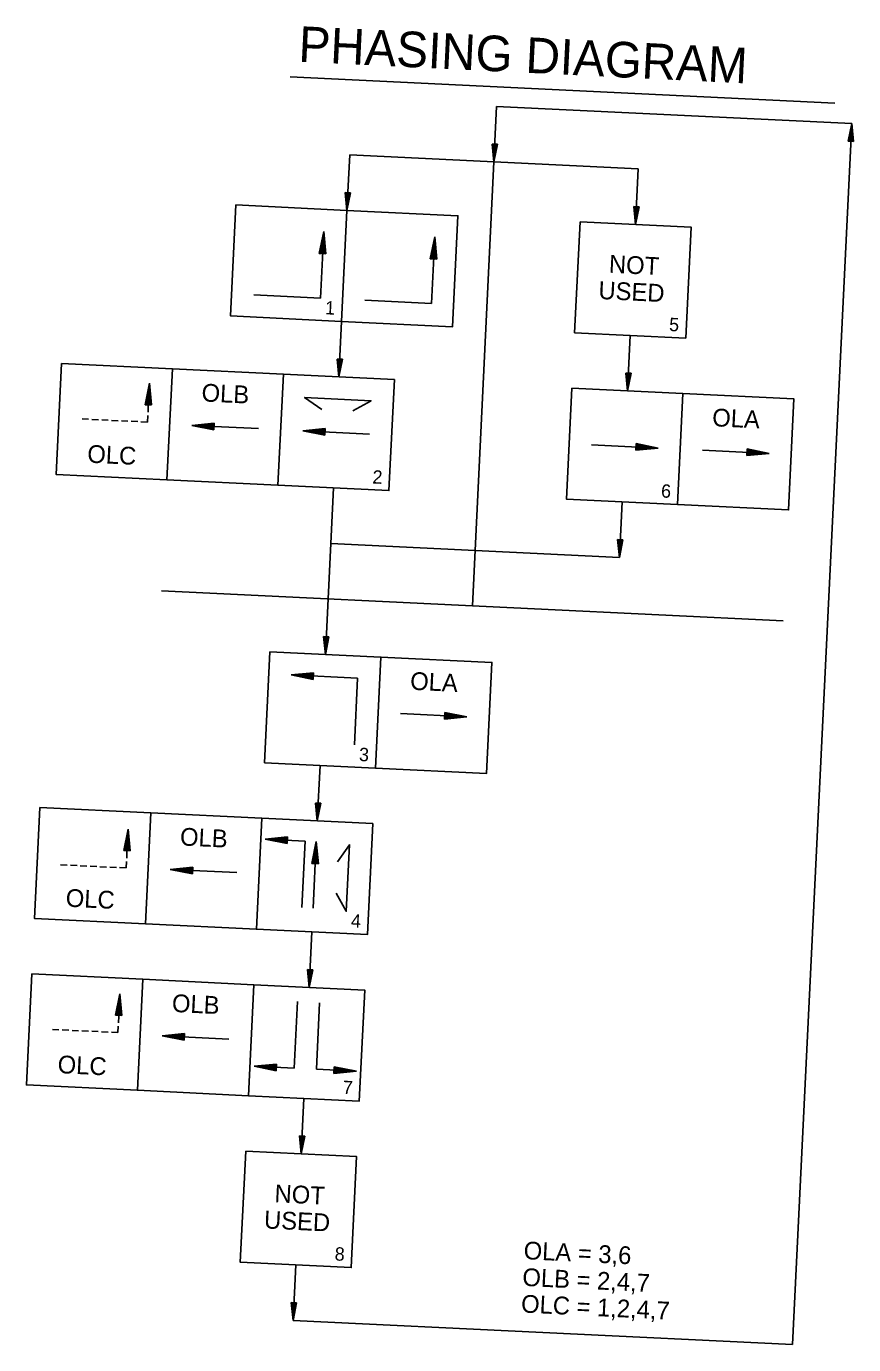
# Model space of a CAD drawing. Extents: x 662220 to 671027, y 641390 to 743815.
# Drawn here: x 662237 to 662423.1, y 642449.9 to 642746.5 of the extents above; entities that cross this region are included whole.
import ezdxf

# ---------------------------------------------------------------- set-up
doc = ezdxf.new("R2010")
doc.units = 0
doc.layers.add('R_Proposed Road Annot', color=7, linetype='Continuous')

msp = doc.modelspace()

# ---------------------------------------------------------------- linework, layer by layer
at = {"layer": 'R_Proposed Road Annot'}
for p, q in [((662296.37, 642735.15), (662418.88, 642729.2)), ((662337.38, 642616.11), (662342.83, 642728.48)), ((662342.83, 642728.48), (662422.74, 642724.6)), ((662422.74, 642724.6), (662409.4, 642449.92)), ((662421.95, 642720.63), (662422.74, 642724.6)), ((662422.05, 642720.63), (662422.71, 642723.93)), ((662422.15, 642720.62), (662422.67, 642723.25)), ((662422.25, 642720.62), (662422.64, 642722.58)), ((662422.84, 642720.59), (662422.64, 642722.58)), ((662422.94, 642720.59), (662422.67, 642723.25)), ((662423.04, 642720.58), (662422.71, 642723.93)), ((662423.14, 642720.58), (662422.74, 642724.6)), ((662341.82, 642720.02), (662342.23, 642716)), ((662343.02, 642719.96), (662341.82, 642720.02)), ((662341.92, 642720.01), (662342.26, 642716.66)), ((662342.02, 642720.01), (662342.29, 642717.35)), ((662342.12, 642720.01), (662342.32, 642718.01)), ((662342.23, 642720), (662342.36, 642718.69)), ((662343.02, 642719.96), (662342.23, 642716)), ((662342.92, 642719.97), (662342.26, 642716.66)), ((662342.82, 642719.97), (662342.29, 642717.35)), ((662342.72, 642719.98), (662342.32, 642718.01)), ((662342.33, 642720), (662342.39, 642719.36)), ((662342.61, 642719.98), (662342.36, 642718.69)), ((662342.51, 642719.99), (662342.39, 642719.36)), ((662421.95, 642720.63), (662423.14, 642720.58)), ((662422.35, 642720.61), (662422.61, 642721.9)), ((662422.45, 642720.61), (662422.58, 642721.24)), ((662422.64, 642720.6), (662422.58, 642721.24)), ((662422.74, 642720.6), (662422.61, 642721.9)), ((662309.16, 642705.09), (662309.77, 642717.57)), ((662309.77, 642717.57), (662374.69, 642714.42)), ((662374.08, 642701.93), (662374.69, 642714.42)), ((662308.75, 642709.11), (662309.16, 642705.09)), ((662309.95, 642709.05), (662308.75, 642709.11)), ((662308.85, 642709.11), (662309.19, 642705.75)), ((662308.96, 642709.1), (662309.22, 642706.44)), ((662309.06, 642709.1), (662309.26, 642707.11)), ((662309.16, 642709.09), (662309.29, 642707.78)), ((662309.95, 642709.05), (662309.16, 642705.09)), ((662309.85, 642709.06), (662309.19, 642705.75)), ((662309.75, 642709.06), (662309.22, 642706.44)), ((662309.26, 642709.09), (662309.32, 642708.45)), ((662309.65, 642709.07), (662309.26, 642707.11)), ((662309.55, 642709.07), (662309.29, 642707.78)), ((662309.45, 642709.08), (662309.32, 642708.45)), ((662373.68, 642705.96), (662374.08, 642701.93)), ((662374.88, 642705.9), (662373.68, 642705.96)), ((662373.78, 642705.95), (662374.11, 642702.6)), ((662373.88, 642705.95), (662374.15, 642703.29)), ((662373.98, 642705.94), (662374.18, 642703.95)), ((662374.08, 642705.94), (662374.21, 642704.63)), ((662374.88, 642705.9), (662374.08, 642701.93)), ((662374.78, 642705.9), (662374.11, 642702.6)), ((662374.67, 642705.91), (662374.15, 642703.29)), ((662374.18, 642705.93), (662374.25, 642705.3)), ((662374.57, 642705.91), (662374.18, 642703.95)), ((662374.47, 642705.92), (662374.21, 642704.63)), ((662374.37, 642705.92), (662374.25, 642705.3)), ((662302.93, 642695.38), (662303.92, 642700.33)), ((662303.88, 642699.5), (662303.06, 642695.37)), ((662303.18, 642695.36), (662303.84, 642698.64)), ((662303.19, 642685.35), (662303.92, 642700.33)), ((662303.84, 642698.64), (662304.18, 642695.32)), ((662304.3, 642695.31), (662303.88, 642699.5)), ((662303.92, 642700.33), (662304.43, 642695.3)), ((662327.9, 642694.16), (662328.89, 642699.12)), ((662328.17, 642684.14), (662328.89, 642699.12)), ((662328.89, 642699.12), (662329.4, 642694.09)), ((662303.8, 642697.81), (662303.31, 642695.36)), ((662303.44, 642695.35), (662303.76, 642696.96)), ((662303.72, 642696.13), (662303.56, 642695.35)), ((662303.8, 642695.33), (662303.72, 642696.13)), ((662303.76, 642696.96), (662303.92, 642695.33)), ((662304.05, 642695.32), (662303.8, 642697.81)), ((662328.85, 642698.29), (662328.03, 642694.16)), ((662328.15, 642694.15), (662328.81, 642697.43)), ((662328.77, 642696.6), (662328.28, 642694.15)), ((662328.41, 642694.14), (662328.73, 642695.75)), ((662328.73, 642695.75), (662328.89, 642694.12)), ((662329.02, 642694.11), (662328.77, 642696.6)), ((662328.81, 642697.43), (662329.15, 642694.1)), ((662329.27, 642694.1), (662328.85, 642698.29)), ((662302.93, 642695.38), (662304.43, 642695.3)), ((662327.9, 642694.16), (662329.4, 642694.09)), ((662328.69, 642694.92), (662328.53, 642694.13)), ((662328.77, 642694.12), (662328.69, 642694.92)), ((662288.21, 642686.08), (662303.19, 642685.35)), ((662313.18, 642684.87), (662328.17, 642684.14)), ((662307.34, 642667.63), (662307.95, 642680.12)), ((662372.26, 642664.48), (662372.87, 642676.96)), ((662306.93, 642671.65), (662307.34, 642667.63)), ((662308.13, 642671.6), (662306.93, 642671.65)), ((662307.03, 642671.65), (662307.37, 642668.3)), ((662307.14, 642671.65), (662307.41, 642668.98)), ((662307.24, 642671.64), (662307.44, 642669.65)), ((662307.34, 642671.64), (662307.47, 642670.33)), ((662308.13, 642671.6), (662307.34, 642667.63)), ((662308.03, 642671.6), (662307.37, 642668.3)), ((662307.93, 642671.61), (662307.41, 642668.98)), ((662307.44, 642671.63), (662307.5, 642670.99)), ((662307.83, 642671.61), (662307.44, 642669.65)), ((662307.73, 642671.62), (662307.47, 642670.33)), ((662307.63, 642671.62), (662307.5, 642670.99)), ((662263.76, 642661.38), (662264.72, 642666.2)), ((662264.72, 642666.2), (662265.21, 642661.31)), ((662371.86, 642668.5), (662372.26, 642664.48)), ((662373.06, 642668.44), (662371.86, 642668.5)), ((662371.96, 642668.5), (662372.3, 642665.15)), ((662372.06, 642668.49), (662372.33, 642665.83)), ((662372.16, 642668.49), (662372.36, 642666.5)), ((662372.26, 642668.48), (662372.39, 642667.17)), ((662373.06, 642668.44), (662372.26, 642664.48)), ((662372.96, 642668.45), (662372.3, 642665.15)), ((662372.85, 642668.45), (662372.33, 642665.83)), ((662372.36, 642668.48), (662372.43, 642667.84)), ((662372.76, 642668.46), (662372.36, 642666.5)), ((662372.65, 642668.46), (662372.39, 642667.17)), ((662372.55, 642668.47), (662372.43, 642667.84)), ((662264.68, 642665.39), (662263.88, 642661.37)), ((662264, 642661.37), (662264.64, 642664.55)), ((662264.6, 642663.74), (662264.12, 642661.36)), ((662264.85, 642661.32), (662264.6, 642663.74)), ((662264.64, 642664.55), (662264.97, 642661.32)), ((662265.09, 642661.31), (662264.68, 642665.39)), ((662263.76, 642661.38), (662265.21, 642661.31)), ((662264.25, 642661.35), (662264.56, 642662.92)), ((662264.52, 642662.11), (662264.37, 642661.35)), ((662264.47, 642661.14), (662264.4, 642659.67)), ((662264.6, 642661.34), (662264.52, 642662.11)), ((662264.56, 642662.92), (662264.72, 642661.33)), ((662249.55, 642658.17), (662251.03, 642658.1)), ((662251.76, 642658.07), (662253.24, 642658)), ((662253.98, 642657.96), (662255.45, 642657.89)), ((662256.19, 642657.85), (662257.66, 642657.78)), ((662258.4, 642657.74), (662259.87, 642657.67)), ((662260.61, 642657.64), (662262.08, 642657.57)), ((662262.82, 642657.53), (662264.3, 642657.46)), ((662264.37, 642658.93), (662264.3, 642657.46)), ((662274.27, 642656.72), (662279.3, 642657.23)), ((662279.3, 642657.1), (662275.11, 642656.68)), ((662279.23, 642655.73), (662279.3, 642657.23)), ((662289.25, 642655.99), (662274.27, 642656.72)), ((662279.23, 642655.73), (662274.27, 642656.72)), ((662275.11, 642656.68), (662279.24, 642655.85)), ((662275.96, 642656.64), (662279.29, 642656.98)), ((662279.24, 642655.98), (662275.96, 642656.64)), ((662279.28, 642656.85), (662276.8, 642656.6)), ((662276.8, 642656.6), (662279.25, 642656.11)), ((662277.64, 642656.56), (662279.28, 642656.72)), ((662279.25, 642656.24), (662277.64, 642656.56)), ((662279.27, 642656.6), (662278.48, 642656.52)), ((662278.48, 642656.52), (662279.26, 642656.36)), ((662299.24, 642655.51), (662304.27, 642656.02)), ((662314.22, 642654.78), (662299.24, 642655.51)), ((662304.2, 642654.52), (662299.24, 642655.51)), ((662304.27, 642655.89), (662300.08, 642655.47)), ((662300.08, 642655.47), (662304.21, 642654.64)), ((662300.94, 642655.43), (662304.26, 642655.76)), ((662304.21, 642654.77), (662300.94, 642655.43)), ((662304.25, 642655.64), (662301.77, 642655.39)), ((662301.77, 642655.39), (662304.22, 642654.89)), ((662302.61, 642655.35), (662304.25, 642655.51)), ((662304.22, 642655.02), (662302.61, 642655.35)), ((662304.24, 642655.38), (662303.45, 642655.3)), ((662303.45, 642655.3), (662304.23, 642655.15)), ((662304.2, 642654.52), (662304.27, 642656.02)), ((662364.17, 642652.36), (662379.15, 642651.63)), ((662374.19, 642652.62), (662374.12, 642651.12)), ((662374.12, 642651.25), (662378.31, 642651.67)), ((662379.15, 642651.63), (662374.12, 642651.12)), ((662377.46, 642651.71), (662374.13, 642651.37)), ((662375.78, 642651.79), (662374.14, 642651.63)), ((662374.14, 642651.5), (662376.62, 642651.75)), ((662374.15, 642651.75), (662374.94, 642651.83)), ((662374.94, 642651.83), (662374.16, 642651.99)), ((662376.62, 642651.75), (662374.17, 642652.24)), ((662374.17, 642652.11), (662375.78, 642651.79)), ((662378.31, 642651.67), (662374.18, 642652.5)), ((662374.18, 642652.37), (662377.46, 642651.71)), ((662374.19, 642652.62), (662379.15, 642651.63)), ((662389.14, 642651.14), (662404.12, 642650.42)), ((662399.16, 642651.41), (662399.09, 642649.91)), ((662399.15, 642651.16), (662402.43, 642650.5)), ((662399.16, 642651.41), (662404.12, 642650.42)), ((662403.28, 642650.46), (662399.16, 642651.28)), ((662399.09, 642650.03), (662403.28, 642650.46)), ((662404.12, 642650.42), (662399.09, 642649.91)), ((662402.43, 642650.5), (662399.1, 642650.16)), ((662400.75, 642650.58), (662399.11, 642650.41)), ((662399.11, 642650.29), (662401.59, 642650.54)), ((662399.12, 642650.54), (662399.91, 642650.62)), ((662399.91, 642650.62), (662399.13, 642650.78)), ((662401.59, 642650.54), (662399.14, 642651.03)), ((662399.14, 642650.9), (662400.75, 642650.58)), ((662304.31, 642605.2), (662306.13, 642642.66)), ((662370.44, 642627.02), (662371.05, 642639.51)), ((662370.04, 642631.05), (662370.44, 642627.02)), ((662371.24, 642630.99), (662370.04, 642631.05)), ((662370.14, 642631.04), (662370.48, 642627.69)), ((662370.24, 642631.04), (662370.51, 642628.38)), ((662370.34, 642631.03), (662370.54, 642629.04)), ((662370.44, 642631.03), (662370.58, 642629.72)), ((662371.24, 642630.99), (662370.44, 642627.02)), ((662371.14, 642630.99), (662370.48, 642627.69)), ((662371.04, 642631), (662370.51, 642628.38)), ((662370.54, 642631.02), (662370.61, 642630.39)), ((662370.94, 642631), (662370.54, 642629.04)), ((662370.83, 642631.01), (662370.58, 642629.72)), ((662370.73, 642631.01), (662370.61, 642630.39)), ((662305.52, 642630.17), (662370.44, 642627.02)), ((662267.46, 642619.51), (662407.29, 642612.72)), ((662303.9, 642609.23), (662304.31, 642605.2)), ((662305.1, 642609.17), (662303.9, 642609.23)), ((662304, 642609.22), (662304.34, 642605.87)), ((662304.11, 642609.22), (662304.37, 642606.56)), ((662304.2, 642609.21), (662304.41, 642607.22)), ((662304.31, 642609.21), (662304.44, 642607.9)), ((662305.1, 642609.17), (662304.31, 642605.2)), ((662305, 642609.18), (662304.34, 642605.87)), ((662304.9, 642609.18), (662304.37, 642606.56)), ((662304.41, 642609.2), (662304.47, 642608.57)), ((662304.8, 642609.18), (662304.41, 642607.22)), ((662304.7, 642609.19), (662304.44, 642607.9)), ((662304.6, 642609.19), (662304.47, 642608.57)), ((662296.57, 642600.57), (662301.61, 642601.08)), ((662301.6, 642600.96), (662297.41, 642600.53)), ((662298.27, 642600.49), (662301.59, 642600.83)), ((662301.53, 642599.58), (662301.61, 642601.08)), ((662311.56, 642599.85), (662296.57, 642600.57)), ((662301.53, 642599.58), (662296.57, 642600.57)), ((662297.41, 642600.53), (662301.54, 642599.71)), ((662301.54, 642599.83), (662298.27, 642600.49)), ((662301.59, 642600.7), (662299.1, 642600.45)), ((662299.1, 642600.45), (662301.55, 642599.96)), ((662299.95, 642600.41), (662301.58, 642600.58)), ((662301.56, 642600.09), (662299.95, 642600.41)), ((662301.57, 642600.45), (662300.78, 642600.37)), ((662300.78, 642600.37), (662301.56, 642600.21)), ((662310.83, 642584.86), (662311.56, 642599.85)), ((662321.18, 642591.87), (662336.16, 642591.14)), ((662331.21, 642592.13), (662331.13, 642590.64)), ((662331.19, 642591.88), (662334.47, 642591.22)), ((662335.33, 642591.18), (662331.2, 642592.01)), ((662331.21, 642592.13), (662336.16, 642591.14)), ((662336.16, 642591.14), (662331.13, 642590.64)), ((662331.14, 642590.76), (662335.33, 642591.18)), ((662331.15, 642591.01), (662333.64, 642591.27)), ((662334.47, 642591.22), (662331.15, 642590.89)), ((662331.16, 642591.27), (662331.96, 642591.35)), ((662332.79, 642591.31), (662331.16, 642591.14)), ((662331.18, 642591.63), (662332.79, 642591.31)), ((662331.96, 642591.35), (662331.18, 642591.5)), ((662333.64, 642591.27), (662331.19, 642591.76)), ((662302.49, 642567.75), (662303.1, 642580.23)), ((662302.08, 642571.77), (662302.49, 642567.75)), ((662303.28, 642571.71), (662302.08, 642571.77)), ((662302.18, 642571.77), (662302.52, 642568.42)), ((662302.29, 642571.76), (662302.56, 642569.1)), ((662302.39, 642571.76), (662302.59, 642569.77)), ((662302.49, 642571.75), (662302.62, 642570.45)), ((662303.28, 642571.71), (662302.49, 642567.75)), ((662303.18, 642571.72), (662302.52, 642568.42)), ((662303.08, 642571.72), (662302.56, 642569.1)), ((662302.59, 642571.75), (662302.65, 642571.11)), ((662302.98, 642571.73), (662302.59, 642569.77)), ((662302.88, 642571.73), (662302.62, 642570.45)), ((662302.78, 642571.74), (662302.65, 642571.11)), ((662258.95, 642561.07), (662259.91, 642565.89)), ((662259.91, 642565.89), (662260.4, 642561)), ((662259.87, 642565.08), (662259.07, 642561.07)), ((662259.19, 642561.06), (662259.83, 642564.25)), ((662259.79, 642563.44), (662259.31, 642561.06)), ((662259.44, 642561.05), (662259.75, 642562.62)), ((662259.75, 642562.62), (662259.91, 642561.03)), ((662260.04, 642561.02), (662259.79, 642563.44)), ((662259.83, 642564.25), (662260.16, 642561.02)), ((662260.28, 642561.01), (662259.87, 642565.08)), ((662290.78, 642563.65), (662295.81, 642564.15)), ((662299.77, 642563.21), (662290.78, 642563.65)), ((662295.73, 642562.65), (662290.78, 642563.65)), ((662295.8, 642564.03), (662291.61, 642563.6)), ((662291.61, 642563.6), (662295.74, 642562.78)), ((662292.47, 642563.56), (662295.8, 642563.9)), ((662295.75, 642562.91), (662292.47, 642563.56)), ((662295.79, 642563.78), (662293.3, 642563.52)), ((662293.3, 642563.52), (662295.75, 642563.03)), ((662294.15, 642563.48), (662295.78, 642563.65)), ((662295.76, 642563.16), (662294.15, 642563.48)), ((662295.78, 642563.52), (662294.98, 642563.44)), ((662294.98, 642563.44), (662295.77, 642563.29)), ((662295.73, 642562.65), (662295.81, 642564.15)), ((662299.04, 642548.23), (662299.77, 642563.21)), ((662301.27, 642558.13), (662302.26, 642563.09)), ((662302.22, 642562.25), (662301.4, 642558.12)), ((662301.54, 642548.11), (662302.26, 642563.09)), ((662302.65, 642558.06), (662302.22, 642562.25)), ((662302.26, 642563.09), (662302.77, 642558.06)), ((662258.95, 642561.07), (662260.4, 642561)), ((662259.71, 642561.81), (662259.56, 642561.04)), ((662259.67, 642560.84), (662259.6, 642559.37)), ((662259.79, 642561.03), (662259.71, 642561.81)), ((662301.52, 642558.12), (662302.18, 642561.39)), ((662302.14, 642560.56), (662301.65, 642558.11)), ((662301.78, 642558.11), (662302.1, 642559.72)), ((662302.1, 642559.72), (662302.27, 642558.08)), ((662302.39, 642558.08), (662302.14, 642560.56)), ((662302.18, 642561.39), (662302.52, 642558.07)), ((662244.74, 642557.87), (662246.22, 642557.8)), ((662246.96, 642557.76), (662248.43, 642557.69)), ((662249.17, 642557.66), (662250.64, 642557.59)), ((662251.38, 642557.55), (662252.85, 642557.48)), ((662253.59, 642557.44), (662255.06, 642557.37)), ((662255.8, 642557.33), (662257.28, 642557.26)), ((662258.01, 642557.23), (662259.49, 642557.16)), ((662259.56, 642558.63), (662259.49, 642557.16)), ((662269.42, 642556.84), (662274.45, 642557.35)), ((662284.4, 642556.11), (662269.42, 642556.84)), ((662274.38, 642555.85), (662269.42, 642556.84)), ((662274.45, 642557.22), (662270.26, 642556.8)), ((662270.26, 642556.8), (662274.39, 642555.97)), ((662271.11, 642556.76), (662274.44, 642557.09)), ((662274.39, 642556.1), (662271.11, 642556.76)), ((662274.43, 642556.97), (662271.95, 642556.72)), ((662271.95, 642556.72), (662274.4, 642556.22)), ((662272.79, 642556.68), (662274.43, 642556.84)), ((662274.4, 642556.35), (662272.79, 642556.68)), ((662274.42, 642556.71), (662273.63, 642556.64)), ((662273.63, 642556.64), (662274.41, 642556.48)), ((662274.38, 642555.85), (662274.45, 642557.35)), ((662301.27, 642558.13), (662302.77, 642558.06)), ((662302.06, 642558.88), (662301.9, 642558.1)), ((662302.14, 642558.09), (662302.06, 642558.88)), ((662300.67, 642530.29), (662301.28, 642542.78)), ((662300.27, 642534.32), (662300.67, 642530.29)), ((662301.46, 642534.26), (662300.27, 642534.32)), ((662300.37, 642534.31), (662300.7, 642530.96)), ((662300.47, 642534.31), (662300.74, 642531.65)), ((662300.57, 642534.3), (662300.77, 642532.31)), ((662300.67, 642534.3), (662300.8, 642532.99)), ((662301.46, 642534.26), (662300.67, 642530.29)), ((662301.36, 642534.26), (662300.7, 642530.96)), ((662301.26, 642534.27), (662300.74, 642531.65)), ((662300.77, 642534.29), (662300.83, 642533.66)), ((662301.16, 642534.27), (662300.77, 642532.31)), ((662301.06, 642534.28), (662300.8, 642532.99)), ((662300.96, 642534.28), (662300.83, 642533.66)), ((662257.09, 642524.04), (662258.05, 642528.86)), ((662258.01, 642528.05), (662257.21, 642524.03)), ((662257.33, 642524.03), (662257.97, 642527.21)), ((662257.97, 642527.21), (662258.3, 642523.98)), ((662258.42, 642523.97), (662258.01, 642528.05)), ((662258.05, 642528.86), (662258.54, 642523.97)), ((662297.28, 642512.11), (662298.01, 642527.09)), ((662302.28, 642511.86), (662303.01, 642526.84)), ((662257.09, 642524.04), (662258.54, 642523.97)), ((662257.93, 642526.4), (662257.45, 642524.02)), ((662257.58, 642524.01), (662257.89, 642525.58)), ((662257.85, 642524.77), (662257.7, 642524.01)), ((662257.81, 642523.81), (662257.73, 642522.33)), ((662257.93, 642524), (662257.85, 642524.77)), ((662257.89, 642525.58), (662258.05, 642523.99)), ((662258.18, 642523.99), (662257.93, 642526.4)), ((662242.88, 642520.84), (662244.36, 642520.76)), ((662245.1, 642520.73), (662246.57, 642520.66)), ((662257.7, 642521.59), (662257.63, 642520.12)), ((662247.31, 642520.62), (662248.78, 642520.55)), ((662249.52, 642520.51), (662250.99, 642520.44)), ((662251.73, 642520.41), (662253.2, 642520.33)), ((662253.94, 642520.3), (662255.42, 642520.23)), ((662256.15, 642520.19), (662257.63, 642520.12)), ((662267.6, 642519.38), (662272.63, 642519.89)), ((662282.59, 642518.66), (662267.6, 642519.38)), ((662272.56, 642518.39), (662267.6, 642519.38)), ((662272.63, 642519.77), (662268.44, 642519.34)), ((662268.44, 642519.34), (662272.57, 642518.52)), ((662269.3, 642519.3), (662272.62, 642519.64)), ((662272.57, 642518.64), (662269.3, 642519.3)), ((662272.61, 642519.51), (662270.13, 642519.26)), ((662270.13, 642519.26), (662272.58, 642518.77)), ((662270.97, 642519.22), (662272.61, 642519.39)), ((662272.59, 642518.9), (662270.97, 642519.22)), ((662272.6, 642519.26), (662271.81, 642519.18)), ((662271.81, 642519.18), (662272.59, 642519.02)), ((662272.56, 642518.39), (662272.63, 642519.89)), ((662288.3, 642512.54), (662293.33, 642513.05)), ((662297.28, 642512.11), (662288.3, 642512.54)), ((662293.25, 642511.55), (662288.3, 642512.54)), ((662293.32, 642512.92), (662289.13, 642512.5)), ((662289.13, 642512.5), (662293.26, 642511.67)), ((662289.99, 642512.46), (662293.31, 642512.8)), ((662293.27, 642511.8), (662289.99, 642512.46)), ((662293.31, 642512.67), (662290.82, 642512.42)), ((662290.82, 642512.42), (662293.27, 642511.93)), ((662291.67, 642512.38), (662293.3, 642512.54)), ((662293.28, 642512.06), (662291.67, 642512.38)), ((662293.3, 642512.42), (662292.5, 642512.34)), ((662292.5, 642512.34), (662293.28, 642512.18)), ((662293.25, 642511.55), (662293.33, 642513.05)), ((662311.27, 642511.43), (662302.28, 642511.86)), ((662306.24, 642510.92), (662306.31, 642512.42)), ((662306.28, 642511.79), (662307.06, 642511.63)), ((662306.29, 642512.04), (662308.74, 642511.55)), ((662307.9, 642511.59), (662306.29, 642511.91)), ((662306.3, 642512.29), (662310.43, 642511.47)), ((662309.58, 642511.51), (662306.3, 642512.17)), ((662311.27, 642511.43), (662306.31, 642512.42)), ((662310.43, 642511.47), (662306.24, 642511.04)), ((662306.24, 642510.92), (662311.27, 642511.43)), ((662306.25, 642511.17), (662309.58, 642511.51)), ((662306.26, 642511.43), (662307.9, 642511.59)), ((662308.74, 642511.55), (662306.26, 642511.3)), ((662307.06, 642511.63), (662306.27, 642511.55)), ((662298.85, 642492.84), (662299.46, 642505.32)), ((662298.45, 642496.86), (662298.85, 642492.84)), ((662299.65, 642496.8), (662298.45, 642496.86)), ((662298.55, 642496.86), (662298.88, 642493.5)), ((662298.65, 642496.85), (662298.92, 642494.19)), ((662298.75, 642496.85), (662298.95, 642494.86)), ((662298.85, 642496.84), (662298.98, 642495.53)), ((662299.65, 642496.8), (662298.85, 642492.84)), ((662299.55, 642496.81), (662298.88, 642493.5)), ((662299.44, 642496.81), (662298.92, 642494.19)), ((662298.95, 642496.84), (662299.02, 642496.2)), ((662299.34, 642496.82), (662298.95, 642494.86)), ((662299.24, 642496.82), (662298.98, 642495.53)), ((662299.14, 642496.83), (662299.02, 642496.2)), ((662297.03, 642455.38), (662297.64, 642467.87)), ((662296.63, 642459.4), (662297.03, 642455.38)), ((662297.83, 642459.35), (662296.63, 642459.4)), ((662296.73, 642459.4), (662297.07, 642456.05)), ((662296.83, 642459.4), (662297.1, 642456.73)), ((662296.93, 642459.39), (662297.13, 642457.4)), ((662297.03, 642459.39), (662297.16, 642458.08)), ((662297.83, 642459.35), (662297.03, 642455.38)), ((662297.73, 642459.35), (662297.07, 642456.05)), ((662297.62, 642459.36), (662297.1, 642456.73)), ((662297.13, 642459.38), (662297.2, 642458.74)), ((662297.52, 642459.36), (662297.13, 642457.4)), ((662297.42, 642459.37), (662297.16, 642458.08)), ((662297.32, 642459.37), (662297.2, 642458.74)), ((662297.03, 642455.38), (662409.4, 642449.92))]:
    msp.add_line(p, q, dxfattribs=at)
for points in [[(662284.19, 642706.3), (662309.16, 642705.09), (662307.95, 642680.12), (662282.98, 642681.33)], [(662309.16, 642705.09), (662334.13, 642703.87), (662332.92, 642678.9), (662307.95, 642680.12)], [(662361.6, 642702.54), (662386.57, 642701.33), (662385.36, 642676.36), (662360.38, 642677.57)], [(662244.91, 642670.66), (662269.88, 642669.45), (662268.67, 642644.48), (662243.7, 642645.69)], [(662269.88, 642669.45), (662294.85, 642668.24), (662293.64, 642643.27), (662268.67, 642644.48)], [(662294.85, 642668.24), (662319.83, 642667.02), (662318.61, 642642.05), (662293.64, 642643.27)], [(662359.78, 642665.08), (662384.75, 642663.87), (662383.54, 642638.9), (662358.57, 642640.11)], [(662384.75, 642663.87), (662409.72, 642662.66), (662408.51, 642637.69), (662383.54, 642638.9)], [(662291.82, 642605.81), (662316.79, 642604.6), (662315.58, 642579.63), (662290.61, 642580.84)], [(662316.79, 642604.6), (662341.76, 642603.39), (662340.55, 642578.41), (662315.58, 642579.63)], [(662240.06, 642570.78), (662265.03, 642569.57), (662263.82, 642544.6), (662238.85, 642545.81)], [(662265.03, 642569.57), (662290, 642568.35), (662288.79, 642543.38), (662263.82, 642544.6)], [(662290, 642568.35), (662314.97, 642567.14), (662313.76, 642542.17), (662288.79, 642543.38)], [(662238.24, 642533.32), (662263.21, 642532.11), (662262, 642507.14), (662237.03, 642508.35)], [(662263.21, 642532.11), (662288.19, 642530.9), (662286.97, 642505.93), (662262, 642507.14)], [(662288.19, 642530.9), (662313.16, 642529.69), (662311.94, 642504.72), (662286.97, 642505.93)], [(662286.37, 642493.44), (662311.34, 642492.23), (662310.12, 642467.26), (662285.15, 642468.47)]]:
    msp.add_lwpolyline(points, close=True, dxfattribs=at)
for points in [[(662303.48, 642660.31), (662299.61, 642663), (662314.59, 642662.27), (662310.47, 642659.97)], [(662306.71, 642551.52), (662309.01, 642547.41), (662309.74, 642562.39), (662307.05, 642558.52)]]:
    msp.add_lwpolyline(points, dxfattribs=at)

# ---------------------------------------------------------------- texts
for s, height, p in [('PHASING DIAGRAM', 8, (662298.14, 642738.54)), ('NOT', 4, (662368.02, 642691.07)), ('USED', 4, (662365.66, 642685.17)), ('1', 3, (662304.18, 642681.72)), ('5', 3, (662381.58, 642677.96)), ('OLB', 4, (662276.38, 642662.13)), ('OLA', 4, (662391.26, 642656.55)), ('OLC', 4, (662250.67, 642648.36)), ('2', 3, (662314.84, 642643.66)), ('6', 3, (662379.77, 642640.51)), ('OLA', 4, (662323.31, 642597.27)), ('3', 3, (662311.81, 642581.23)), ('OLB', 4, (662271.53, 642562.24)), ('OLC', 4, (662245.82, 642548.47)), ('4', 3, (662309.99, 642543.78)), ('OLB', 4, (662269.71, 642524.79)), ('OLC', 4, (662244, 642511.02)), ('7', 3, (662308.17, 642506.32)), ('NOT', 4, (662292.79, 642481.97)), ('USED', 4, (662290.43, 642476.08)), ('8', 3, (662306.35, 642468.87)), ('OLA = 3,6', 4, (662348.84, 642469.16)), ('OLB = 2,4,7', 4, (662348.55, 642463.16)), ('OLC = 1,2,4,7', 4, (662348.26, 642457.17))]:
    msp.add_text(s, height=height, rotation=357.2199, dxfattribs=at).set_placement(p)

doc.saveas('drawing.dxf')
